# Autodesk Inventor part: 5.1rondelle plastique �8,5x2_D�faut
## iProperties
Created: 2011-01
Part Number: 5.1rondelle plastique �8,5x2_D�faut
Document SubType Name: Modeling
Designer: eric
Density: 1 g/cm^3
Mass: 0.851175 g
Surface Area: 7.41023 cm^2
Volume: 0.851175 cm^3
Author: eric
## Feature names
1. Base1
